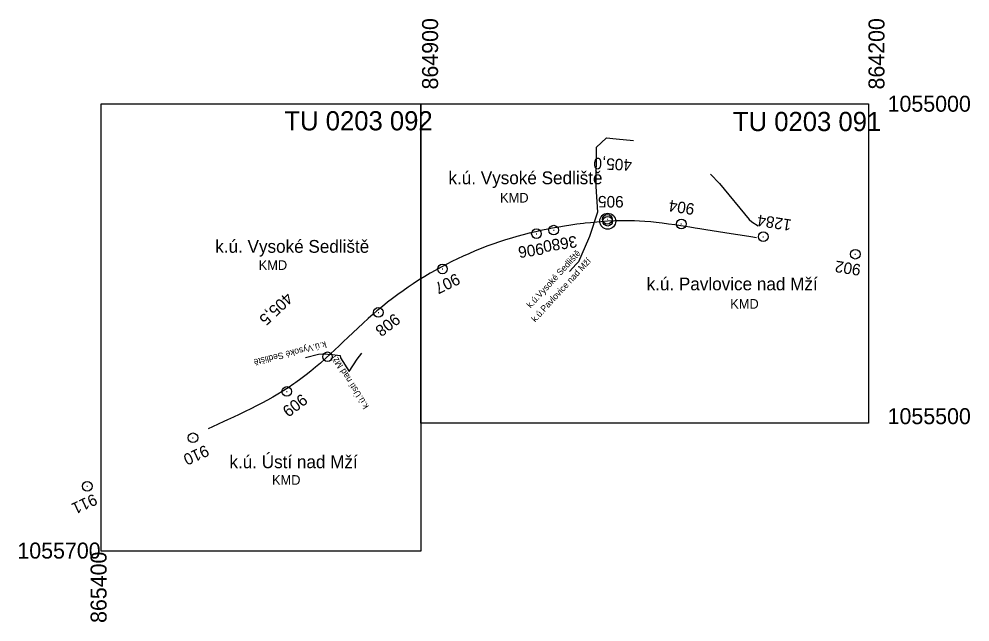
# Model space of a CAD drawing. Extents: x -867628 to -843257, y -1065611 to -1039859.
# Drawn here: x -865528 to -864041, y -1055811 to -1054867 of the extents above; entities that cross this region are included whole.
import ezdxf

# ---------------------------------------------------------------- set-up
doc = ezdxf.new("R2010")
doc.units = 0
for name, color, linetype in [('Vrstva 1', 7, 'Continuous'), ('Vrstva 10', 7, 'Continuous'), ('Vrstva 55', 7, 'Continuous'), ('Vrstva 62', 7, 'Continuous'), ('Vrstva 63', 7, 'Continuous'), ('Vrstva 7', 7, 'Continuous')]:
    doc.layers.add(name, color=color, linetype=linetype)

msp = doc.modelspace()

# ---------------------------------------------------------------- linework, layer by layer
at = {"layer": 'Vrstva 1'}
msp.add_lwpolyline([(-864374.9, -1055209.6), (-864384.1, -1055208.1), (-864394.1, -1055206.6), (-864404.2, -1055205), (-864414.5, -1055203.4), (-864424.7, -1055201.8), (-864434.6, -1055200.3), (-864444.7, -1055198.7), (-864454.6, -1055197.1), (-864463.6, -1055195.7), (-864470.9, -1055194.6), (-864479.4, -1055193.3), (-864486.2, -1055192.2), (-864493.2, -1055191.1), (-864502.9, -1055189.6), (-864512.7, -1055188.2), (-864522.7, -1055186.9), (-864531.9, -1055185.8), (-864540.4, -1055185), (-864549.7, -1055184.2), (-864558, -1055183.6), (-864565.8, -1055183.2), (-864574, -1055183), (-864585.5, -1055183), (-864596.4, -1055183.3), (-864608.2, -1055183.9), (-864618, -1055184.6), (-864624.9, -1055185.1), (-864634.6, -1055186.1), (-864643.3, -1055187.1), (-864645.9, -1055187.4), (-864655.9, -1055188.6), (-864665.7, -1055190), (-864675.5, -1055191.5), (-864684.2, -1055193), (-864694.1, -1055194.8), (-864704, -1055196.7), (-864712.8, -1055198.6), (-864720.4, -1055200.3), (-864730.4, -1055202.6), (-864740.1, -1055205.1), (-864749.7, -1055207.7), (-864758, -1055210.1), (-864767.5, -1055213), (-864777.1, -1055216.2), (-864787.2, -1055219.7), (-864796.6, -1055223.1), (-864805.7, -1055226.6), (-864815.1, -1055230.4), (-864824.9, -1055234.6), (-864833.6, -1055238.5), (-864842.7, -1055242.7), (-864851.3, -1055246.9), (-864859.4, -1055251.1), (-864868.4, -1055255.8), (-864876.7, -1055260.4), (-864885.4, -1055265.3), (-864893.8, -1055270.4), (-864903.5, -1055276.3), (-864911.8, -1055281.7), (-864919.9, -1055287.1), (-864927.8, -1055292.6), (-864936, -1055298.5), (-864944.1, -1055304.5), (-864952, -1055310.6), (-864960, -1055317), (-864968.7, -1055324.2), (-864974.6, -1055329.3), (-864982.5, -1055336.2), (-864990.4, -1055343.5), (-864998.3, -1055350.9), (-865005.9, -1055358), (-865014, -1055365.8), (-865020.7, -1055372.1), (-865027.5, -1055378.6), (-865034.4, -1055385.2), (-865041.2, -1055391.5), (-865049, -1055398.6), (-865057, -1055405.7), (-865064.5, -1055412.1), (-865072.1, -1055418.4), (-865079.3, -1055424.1), (-865087.7, -1055430.4), (-865095.3, -1055436), (-865098.6, -1055438.3), (-865107.6, -1055444.4), (-865116.6, -1055450.1), (-865123.6, -1055454.4), (-865131.6, -1055459.2), (-865139.8, -1055463.8), (-865148.7, -1055468.6), (-865156.9, -1055472.8), (-865165.7, -1055477.3), (-865174.7, -1055481.6), (-865183.9, -1055486), (-865192.9, -1055490.2), (-865202.3, -1055494.5), (-865207.9, -1055497.1), (-865216.9, -1055501.2), (-865226, -1055505.4), (-865232.5, -1055508.4)], dxfattribs=at)
at = {"layer": 'Vrstva 55'}
for points in [[(-864625.6, -1055068.5), (-864609.8, -1055053.3), (-864594.5, -1055055), (-864567.3, -1055057.3)], [(-864625.6, -1055068.5), (-864626.2, -1055129.7), (-864623.8, -1055169.6), (-864636.4, -1055207.6), (-864637.6, -1055211.4), (-864653.5, -1055247.1), (-864657.2, -1055251.1), (-864667.6, -1055262.5)], [(-864447, -1055110), (-864432.8, -1055124.8), (-864386.4, -1055181.3), (-864382.4, -1055184.8), (-864372.7, -1055190.9)], [(-865080.6, -1055396.8), (-865060.3, -1055391.6), (-865053.5, -1055391.3), (-865038.4, -1055392.5), (-865030.2, -1055393.6), (-865026.3, -1055394.1), (-865025.5, -1055397.4), (-865012, -1055418.7)], [(-865012, -1055418.7), (-864999.6, -1055399.4), (-864992.1, -1055390)]]:
    msp.add_lwpolyline(points, dxfattribs=at)
at = {"layer": 'Vrstva 62'}
for points in [[(-864900, -1055000), (-864900, -1055700), (-865400, -1055700), (-865400, -1055000)], [(-864900, -1055000), (-864200, -1055000), (-864200, -1055500), (-864900, -1055500)]]:
    msp.add_lwpolyline(points, close=True, dxfattribs=at)
at = {"layer": 'Vrstva 63'}
for p, q in [((-864608.9, -1055180.7), (-864607.9, -1055180.7)), ((-864493.2, -1055188.1), (-864492.2, -1055188.1)), ((-864719.7, -1055203.3), (-864718.7, -1055203.3)), ((-864692.7, -1055197.8), (-864691.7, -1055197.8)), ((-864365.1, -1055208), (-864364.1, -1055208)), ((-864221.2, -1055235.4), (-864220.2, -1055235.4)), ((-864866.7, -1055258.4), (-864865.7, -1055258.4)), ((-864966.9, -1055326.5), (-864965.9, -1055326.5)), ((-865110.1, -1055450.2), (-865109.1, -1055450.2)), ((-865256.9, -1055522.7), (-865255.9, -1055522.7)), ((-865422.2, -1055598.5), (-865421.2, -1055598.5))]:
    msp.add_line(p, q, dxfattribs=at)
for centre in [(-864608.4, -1055180.7), (-864692.2, -1055197.8), (-864492.7, -1055188.1), (-864719.2, -1055203.3), (-864364.6, -1055208), (-864220.7, -1055235.4), (-864866.2, -1055258.4), (-864966.4, -1055326.5), (-865109.6, -1055450.2), (-865256.4, -1055522.7), (-865421.7, -1055598.5)]:
    msp.add_circle(centre, 7.56, dxfattribs=at)
at = {"layer": 'Vrstva 7'}
for centre, radius in [((-864607.8, -1055183.8), 12.5), ((-864607.8, -1055183.8), 7.52), ((-865046, -1055395.9), 7.5)]:
    msp.add_circle(centre, radius, dxfattribs=at)

# ---------------------------------------------------------------- texts
at = {"layer": 'Vrstva 10'}
for p in [(-864776.1, -1055154.6), (-865153.6, -1055260), (-864416.2, -1055320.6), (-865132.8, -1055596.1)]:
    msp.add_text('KMD', height=15, dxfattribs=at).set_placement(p)
at = {"layer": 'Vrstva 55'}
for s, p in [('k.ú. Vysoké Sedliště', (-864856.8, -1055125.9)), ('k.ú. Vysoké Sedliště', (-865221.5, -1055233.2)), ('k.ú. Pavlovice nad Mží', (-864547, -1055291.9)), ('k.ú. Ústí nad Mží', (-865199.3, -1055570.2))]:
    msp.add_text(s, height=20, dxfattribs=at).set_placement(p)
for s, rotation, p in [('k.ú.Vysoké Sedliště', 47.4372, (-864728.3, -1055320.5)), ('k.ú.Pavlovice nad Mží', 47.4372, (-864721.1, -1055342.5)), ('k.ú.Vysoké Sedliště', 194.2282, (-865049.1, -1055371.5)), ('k.ú.Ústí nad Mží', 122.3212, (-864980.8, -1055473.5))]:
    msp.add_text(s, height=10, rotation=rotation, dxfattribs=at).set_placement(p)
at = {"layer": 'Vrstva 62'}
for s, p in [('864900', (-864873.1, -1054977.7)), ('864200', (-864175, -1054977.7)), ('865400', (-865391.4, -1055812.3))]:
    msp.add_text(s, height=25, rotation=90, dxfattribs=at).set_placement(p)
for s, height, p in [('1055000', 25, (-864170.1, -1055012.5)), ('TU 0203 092', 30, (-865113.4, -1055041.7)), ('TU 0203 091', 30, (-864412, -1055042.8)), ('1055500', 25, (-864170.1, -1055501.3)), ('1055700', 25, (-865530.9, -1055711.6))]:
    msp.add_text(s, height=height, dxfattribs=at).set_placement(p)
at = {"layer": 'Vrstva 63'}
for s, rotation, p in [('905', 179.8454, (-864582.8, -1055144.4)), ('904', 171.1046, (-864471, -1055156.5)), ('1284', 171.114, (-864319.3, -1055181.5)), ('3680', 188.8238, (-864657.1, -1055206.4)), ('906', 188.8238, (-864709.2, -1055217.7)), ('902', 171.114, (-864211, -1055251.6)), ('907', 206.0163, (-864844.5, -1055264.6)), ('908', 217.6461, (-864941.2, -1055326.9)), ('909', 217.1538, (-865086.1, -1055452.7)), ('910', 204.7098, (-865236.7, -1055533.3)), ('911', 204.9957, (-865411.5, -1055609.6))]:
    msp.add_text(s, height=18, rotation=rotation, dxfattribs=at).set_placement(p)
at = {"layer": 'Vrstva 7'}
for s, rotation, p in [('405,0', 177.3276, (-864569.5, -1055087.1)), ('405,5', 223.3335, (-865110.4, -1055293.9))]:
    msp.add_text(s, height=18, rotation=rotation, dxfattribs=at).set_placement(p)

doc.saveas('drawing.dxf')
